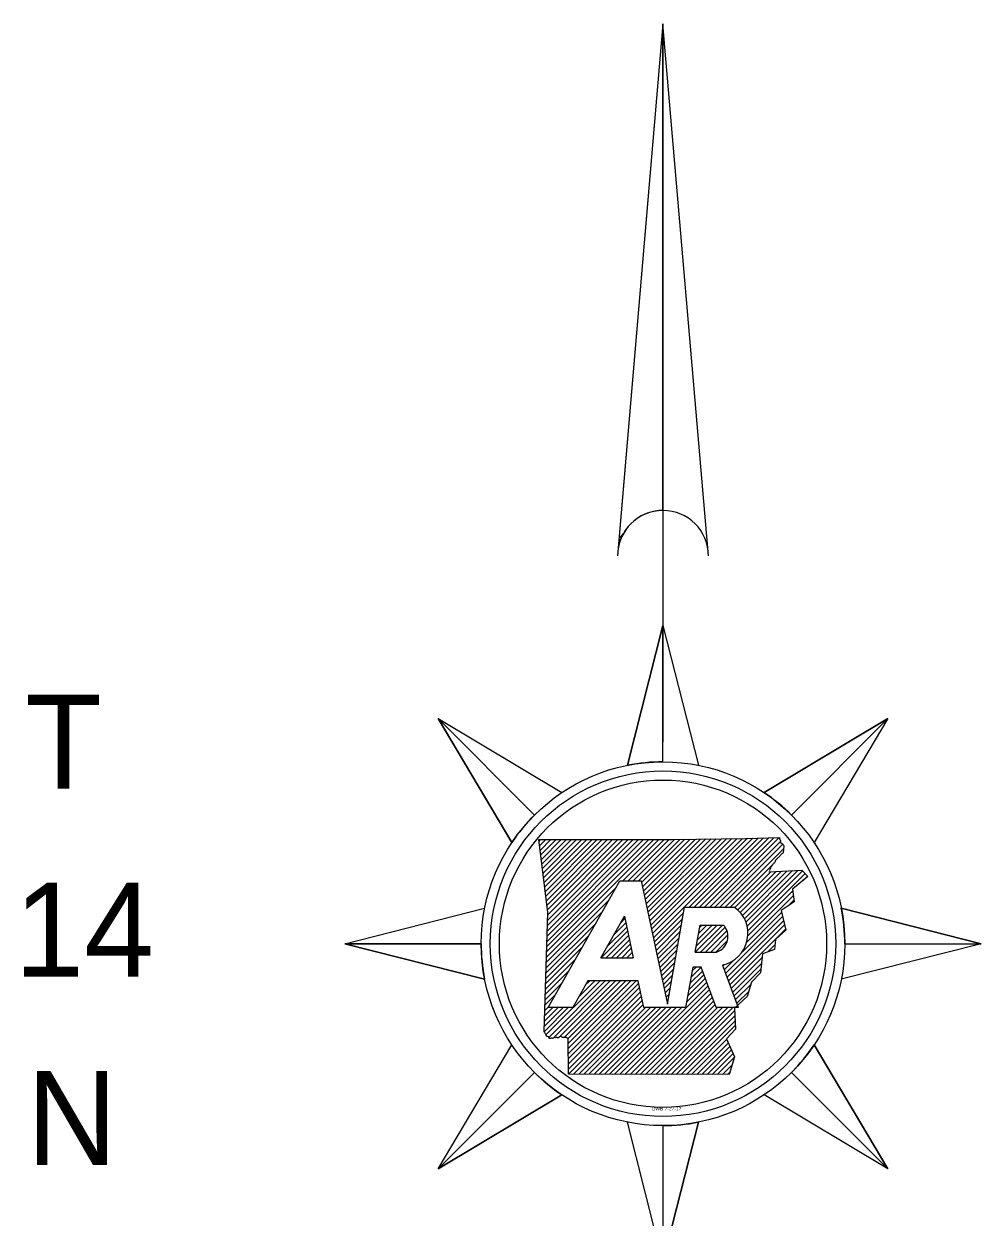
# Model space of a CAD drawing. Extents: x 309348 to 309445, y 336383 to 336484.
# Drawn here: x 309372.414 to 309374.142, y 336389.15 to 336391.302 of the extents above; entities that cross this region are included whole.
import ezdxf

# ---------------------------------------------------------------- set-up
doc = ezdxf.new("R2010")
doc.units = 0
doc.layers.add('R_Annotation', color=7, linetype='Continuous')

msp = doc.modelspace()

# ---------------------------------------------------------------- linework, layer by layer
at = {"layer": 'R_Annotation'}
for p, q in [((309373.5677, 336391.302), (309373.4868, 336390.3563)), ((309373.5677, 336391.302), (309373.5677, 336390.0068)), ((309373.5677, 336390.4244), (309373.5677, 336391.302)), ((309373.488, 336390.3695), (309373.4917, 336390.3732)), ((309373.4884, 336390.3745), (309373.4959, 336390.382)), ((309373.5677, 336390.217), (309373.5038, 336389.9647)), ((309373.5677, 336389.971), (309373.5677, 336390.217)), ((309373.1617, 336390.0489), (309373.3357, 336389.8749)), ((309373.3357, 336389.8749), (309373.1617, 336390.0489)), ((309373.1617, 336390.0489), (309373.295, 336389.8253)), ((309373.9737, 336390.0489), (309373.7501, 336389.9156)), ((309373.7997, 336389.8749), (309373.9737, 336390.0489)), ((309373.7997, 336389.8749), (309373.9737, 336390.0489)), ((309373.539, 336389.7072), (309373.6638, 336389.8321)), ((309373.5406, 336389.6996), (309373.6733, 336389.8322)), ((309373.5422, 336389.6919), (309373.6827, 336389.8324)), ((309373.5439, 336389.6843), (309373.6921, 336389.8325)), ((309373.5455, 336389.6766), (309373.7016, 336389.8327)), ((309373.5471, 336389.669), (309373.711, 336389.8328)), ((309373.5488, 336389.6613), (309373.7204, 336389.833)), ((309373.5504, 336389.6537), (309373.7299, 336389.8332)), ((309373.6149, 336389.7089), (309373.7394, 336389.8334)), ((309373.6241, 336389.7089), (309373.7489, 336389.8337)), ((309373.6334, 336389.7089), (309373.7584, 336389.8339)), ((309373.6427, 336389.7089), (309373.7679, 336389.8341)), ((309373.652, 336389.7089), (309373.7774, 336389.8343)), ((309373.344, 336389.8278), (309373.3469, 336389.8307)), ((309373.3451, 336389.8195), (309373.3562, 336389.8307)), ((309373.3461, 336389.8113), (309373.3655, 336389.8307)), ((309373.3471, 336389.803), (309373.3748, 336389.8307)), ((309373.3482, 336389.7948), (309373.384, 336389.8307)), ((309373.3492, 336389.7865), (309373.3933, 336389.8307)), ((309373.3502, 336389.7783), (309373.4026, 336389.8307)), ((309373.3512, 336389.77), (309373.4119, 336389.8306)), ((309373.3523, 336389.7618), (309373.4211, 336389.8306)), ((309373.3533, 336389.7535), (309373.4304, 336389.8306)), ((309373.3543, 336389.7453), (309373.4397, 336389.8306)), ((309373.3554, 336389.737), (309373.449, 336389.8306)), ((309373.3564, 336389.7288), (309373.4582, 336389.8306)), ((309373.3574, 336389.7205), (309373.4675, 336389.8306)), ((309373.3577, 336389.628), (309373.5605, 336389.8308)), ((309373.358, 336389.6376), (309373.5512, 336389.8308)), ((309373.3584, 336389.6472), (309373.5419, 336389.8308)), ((309373.3584, 336389.7123), (309373.4768, 336389.8306)), ((309373.3587, 336389.6568), (309373.5326, 336389.8307)), ((309373.359, 336389.6664), (309373.5233, 336389.8307)), ((309373.3593, 336389.676), (309373.514, 336389.8307)), ((309373.3595, 336389.704), (309373.4861, 336389.8306)), ((309373.3596, 336389.6856), (309373.5047, 336389.8307)), ((309373.3599, 336389.6952), (309373.4954, 336389.8307)), ((309373.4955, 336389.7566), (309373.5698, 336389.8308)), ((309373.5048, 336389.7566), (309373.5791, 336389.8308)), ((309373.5141, 336389.7566), (309373.5884, 336389.8309)), ((309373.5234, 336389.7566), (309373.5979, 336389.8311)), ((309373.5291, 336389.7531), (309373.6073, 336389.8312)), ((309373.5308, 336389.7454), (309373.6167, 336389.8314)), ((309373.5324, 336389.7378), (309373.6261, 336389.8315)), ((309373.534, 336389.7301), (309373.6356, 336389.8317)), ((309373.5357, 336389.7225), (309373.645, 336389.8318)), ((309373.5373, 336389.7148), (309373.6544, 336389.8319)), ((309373.6613, 336389.7089), (309373.7795, 336389.8271)), ((309373.6705, 336389.7089), (309373.784, 336389.8223)), ((309373.6798, 336389.7089), (309373.7852, 336389.8142)), ((309373.6891, 336389.7089), (309373.764, 336389.7838)), ((309373.6975, 336389.708), (309373.7622, 336389.7727)), ((309373.7026, 336389.7038), (309373.772, 336389.7732)), ((309373.7071, 336389.6991), (309373.7817, 336389.7737)), ((309373.7111, 336389.6938), (309373.7915, 336389.7742)), ((309373.7146, 336389.688), (309373.8013, 336389.7747)), ((309373.7174, 336389.6815), (309373.8111, 336389.7752)), ((309373.7196, 336389.6744), (309373.8199, 336389.7747)), ((309373.7208, 336389.6663), (309373.8242, 336389.7698)), ((309373.3605, 336389.528), (309373.4899, 336389.7566)), ((309373.4899, 336389.7566), (309373.5284, 336389.7566)), ((309373.8201, 336389.7564), (309373.8286, 336389.7648)), ((309373.3574, 336389.6184), (309373.4826, 336389.7437)), ((309373.7189, 336389.6459), (309373.8032, 336389.7301)), ((309373.7209, 336389.6571), (309373.8021, 336389.7383)), ((309373.3571, 336389.6088), (309373.4705, 336389.7223)), ((309373.6065, 336389.7089), (309373.6964, 336389.7089)), ((309373.7928, 336389.7104), (309373.8042, 336389.7219)), ((309374.1418, 336389.6429), (309373.8895, 336389.7068)), ((309373.3568, 336389.5992), (309373.4584, 336389.7009)), ((309373.4557, 336389.6177), (309373.498, 336389.6925)), ((309373.4915, 336389.6808), (309373.4989, 336389.6883)), ((309373.552, 336389.646), (309373.6047, 336389.6987)), ((309373.5537, 336389.6384), (309373.6027, 336389.6875)), ((309373.6806, 336389.589), (309373.7835, 336389.6919)), ((309373.6831, 336389.5822), (309373.7852, 336389.6844)), ((309373.7109, 336389.6285), (309373.7818, 336389.6994)), ((309373.3564, 336389.5896), (309373.4463, 336389.6795)), ((309373.4561, 336389.6177), (309373.5038, 336389.6654)), ((309373.4672, 336389.638), (309373.5022, 336389.673)), ((309373.4793, 336389.6594), (309373.5006, 336389.6807)), ((309373.5553, 336389.6308), (309373.6008, 336389.6762)), ((309373.5569, 336389.6231), (309373.5988, 336389.665)), ((309373.626, 336389.6278), (309373.6749, 336389.6766)), ((309373.6279, 336389.639), (309373.6656, 336389.6766)), ((309373.6299, 336389.6502), (309373.6563, 336389.6766)), ((309373.6318, 336389.6614), (309373.647, 336389.6766)), ((309373.6338, 336389.6727), (309373.6377, 336389.6766)), ((309373.6345, 336389.6766), (309373.6767, 336389.6766)), ((309373.6353, 336389.6278), (309373.68, 336389.6725)), ((309373.6446, 336389.6278), (309373.6831, 336389.6663)), ((309373.6856, 336389.5755), (309373.787, 336389.6768)), ((309373.6881, 336389.5687), (309373.7887, 336389.6693)), ((309372.9935, 336389.6429), (309373.2396, 336389.6429)), ((309373.2396, 336389.6429), (309372.9935, 336389.6429)), ((309372.9935, 336389.6429), (309373.2459, 336389.579)), ((309373.3561, 336389.58), (309373.4342, 336389.6581)), ((309373.4654, 336389.6177), (309373.5055, 336389.6577)), ((309373.4747, 336389.6177), (309373.5071, 336389.6501)), ((309373.484, 336389.6177), (309373.5087, 336389.6424)), ((309373.5586, 336389.6155), (309373.5969, 336389.6537)), ((309373.5602, 336389.6078), (309373.5949, 336389.6425)), ((309373.6539, 336389.6278), (309373.6849, 336389.6588)), ((309373.6632, 336389.6278), (309373.6841, 336389.6487)), ((309373.757, 336389.6283), (309373.77, 336389.6413)), ((309373.8958, 336389.6429), (309374.1418, 336389.6429)), ((309373.8958, 336389.6429), (309374.1418, 336389.6429)), ((309373.3558, 336389.5704), (309373.422, 336389.6367)), ((309373.4557, 336389.6177), (309373.514, 336389.6177)), ((309373.4933, 336389.6177), (309373.5104, 336389.6348)), ((309373.5025, 336389.6177), (309373.512, 336389.6271)), ((309373.5118, 336389.6177), (309373.5137, 336389.6195)), ((309373.5619, 336389.6002), (309373.5929, 336389.6313)), ((309373.5635, 336389.5925), (309373.591, 336389.62)), ((309373.626, 336389.6278), (309373.6645, 336389.6278)), ((309373.6906, 336389.5619), (309373.7463, 336389.6176)), ((309373.3555, 336389.5608), (309373.4099, 336389.6153)), ((309373.5651, 336389.5849), (309373.589, 336389.6088)), ((309373.5668, 336389.5773), (309373.5871, 336389.5976)), ((309373.618, 336389.5821), (309373.6366, 336389.6007)), ((309373.62, 336389.5933), (309373.6273, 336389.6007)), ((309373.6368, 336389.6007), (309373.6213, 336389.6007)), ((309373.6637, 336389.528), (309373.6368, 336389.6007)), ((309373.6749, 336389.6045), (309373.7032, 336389.528)), ((309373.6756, 336389.6026), (309373.6784, 336389.6054)), ((309373.6781, 336389.5958), (309373.6958, 336389.6135)), ((309373.6931, 336389.5551), (309373.7453, 336389.6073)), ((309373.6956, 336389.5484), (309373.7442, 336389.5969)), ((309373.3552, 336389.5513), (309373.3978, 336389.5939)), ((309373.3565, 336389.4784), (309373.4541, 336389.5759)), ((309373.3621, 336389.4746), (309373.4634, 336389.5759)), ((309373.3687, 336389.472), (309373.4726, 336389.5759)), ((309373.3797, 336389.4738), (309373.4819, 336389.5759)), ((309373.3892, 336389.4739), (309373.4912, 336389.5759)), ((309373.3964, 336389.4719), (309373.5005, 336389.5759)), ((309373.3968, 336389.4537), (309373.519, 336389.5759)), ((309373.3968, 336389.4629), (309373.5098, 336389.5759)), ((309373.4321, 336389.5759), (309373.4049, 336389.528)), ((309373.4154, 336389.5465), (309373.4448, 336389.5759)), ((309373.4275, 336389.5679), (309373.4355, 336389.5759)), ((309373.523, 336389.5759), (309373.4321, 336389.5759)), ((309373.5684, 336389.5696), (309373.5851, 336389.5863)), ((309373.57, 336389.562), (309373.5832, 336389.5751)), ((309373.6121, 336389.5484), (309373.6443, 336389.5805)), ((309373.6141, 336389.5596), (309373.6418, 336389.5873)), ((309373.6161, 336389.5709), (309373.6393, 336389.5941)), ((309373.3549, 336389.5417), (309373.3857, 336389.5725)), ((309373.3968, 336389.4444), (309373.5239, 336389.5715)), ((309373.3968, 336389.4351), (309373.5256, 336389.5639)), ((309373.3968, 336389.4259), (309373.5272, 336389.5562)), ((309373.4897, 336389.4074), (309373.6493, 336389.567)), ((309373.4989, 336389.4073), (309373.6518, 336389.5602)), ((309373.5082, 336389.4073), (309373.6543, 336389.5534)), ((309373.5717, 336389.5543), (309373.5812, 336389.5638)), ((309373.5733, 336389.5467), (309373.5792, 336389.5526)), ((309373.6102, 336389.5372), (309373.6468, 336389.5737)), ((309373.6981, 336389.5416), (309373.7266, 336389.57)), ((309373.7006, 336389.5348), (309373.7226, 336389.5568)), ((309373.3545, 336389.5321), (309373.3736, 336389.5511)), ((309373.3969, 336389.4166), (309373.5288, 336389.5486)), ((309373.397, 336389.4075), (309373.5305, 336389.541)), ((309373.4063, 336389.4075), (309373.5321, 336389.5333)), ((309373.5175, 336389.4073), (309373.6568, 336389.5466)), ((309373.5267, 336389.4073), (309373.6593, 336389.5399)), ((309373.536, 336389.4073), (309373.6618, 336389.5331)), ((309373.5749, 336389.539), (309373.5773, 336389.5414)), ((309373.3531, 336389.4842), (309373.3968, 336389.528)), ((309373.3533, 336389.4937), (309373.3875, 336389.528)), ((309373.3536, 336389.5033), (309373.3783, 336389.528)), ((309373.3539, 336389.5129), (309373.369, 336389.528)), ((309373.3542, 336389.5225), (309373.3615, 336389.5297)), ((309373.4049, 336389.528), (309373.3605, 336389.528)), ((309373.4156, 336389.4075), (309373.536, 336389.528)), ((309373.4248, 336389.4075), (309373.5453, 336389.528)), ((309373.4341, 336389.4075), (309373.5546, 336389.528)), ((309373.4433, 336389.4074), (309373.5639, 336389.528)), ((309373.4526, 336389.4074), (309373.5731, 336389.528)), ((309373.4619, 336389.4074), (309373.5824, 336389.528)), ((309373.4711, 336389.4074), (309373.5917, 336389.528)), ((309373.4804, 336389.4074), (309373.601, 336389.528)), ((309373.6086, 336389.528), (309373.5332, 336389.528)), ((309373.5453, 336389.4073), (309373.6659, 336389.528)), ((309373.5545, 336389.4073), (309373.6752, 336389.528)), ((309373.5638, 336389.4072), (309373.6845, 336389.528)), ((309373.5731, 336389.4072), (309373.6938, 336389.528)), ((309373.5823, 336389.4072), (309373.6969, 336389.5218)), ((309373.5916, 336389.4072), (309373.6973, 336389.5129)), ((309373.7032, 336389.528), (309373.6637, 336389.528)), ((309373.6008, 336389.4072), (309373.6977, 336389.504)), ((309373.6101, 336389.4072), (309373.6981, 336389.4952)), ((309373.6194, 336389.4071), (309373.6829, 336389.4707)), ((309373.6286, 336389.4071), (309373.6858, 336389.4642)), ((309373.6379, 336389.4071), (309373.6886, 336389.4578)), ((309373.6472, 336389.4071), (309373.6915, 336389.4514)), ((309373.6564, 336389.4071), (309373.6943, 336389.445)), ((309373.9737, 336389.2369), (309373.8404, 336389.4605)), ((309373.6657, 336389.4071), (309373.6967, 336389.4381)), ((309373.675, 336389.4071), (309373.6925, 336389.4246)), ((309373.1617, 336389.2369), (309373.3357, 336389.4109)), ((309373.3357, 336389.4109), (309373.1617, 336389.2369)), ((309373.6842, 336389.407), (309373.6883, 336389.4112)), ((309373.7997, 336389.4109), (309373.9737, 336389.2369)), ((309373.7997, 336389.4109), (309373.9737, 336389.2369)), ((309373.1617, 336389.2369), (309373.3853, 336389.3702)), ((309373.5677, 336389.0687), (309373.6316, 336389.3211)), ((309373.5677, 336389.3148), (309373.5677, 336389.3148)), ((309373.5677, 336389.3148), (309373.5677, 336388.2645)), ((309373.5677, 336389.3148), (309373.5677, 336389.0687))]:
    msp.add_line(p, q, dxfattribs=at)
for points in [[(309373.6497, 336390.3424), (309373.5677, 336391.302), (309373.4857, 336390.3424)], [(309373.5038, 336389.9647), (309373.5677, 336390.217), (309373.6316, 336389.9647)], [(309373.295, 336389.8253), (309373.1617, 336390.0489), (309373.3853, 336389.9156)], [(309373.7501, 336389.9156), (309373.9737, 336390.0489), (309373.8404, 336389.8253)], [(309373.3437, 336389.8307), (309373.4717, 336389.8306), (309373.5841, 336389.8309), (309373.7166, 336389.8329), (309373.778, 336389.8343)], [(309373.353, 336389.4843), (309373.3601, 336389.6991), (309373.3437, 336389.8307)], [(309373.8182, 336389.7755), (309373.8293, 336389.7639), (309373.8017, 336389.7412), (309373.8047, 336389.7183), (309373.781, 336389.7027), (309373.7891, 336389.6675), (309373.7708, 336389.6508), (309373.7692, 336389.6327), (309373.747, 336389.6247), (309373.7436, 336389.5905), (309373.7276, 336389.5734), (309373.7199, 336389.5477), (309373.6967, 336389.5264), (309373.6984, 336389.4889), (309373.6826, 336389.4712), (309373.697, 336389.439), (309373.6871, 336389.407)], [(309373.759, 336389.7725), (309373.8191, 336389.7756)], [(309373.5284, 336389.7566), (309373.576, 336389.5341), (309373.6065, 336389.7089)], [(309373.2459, 336389.579), (309372.9935, 336389.6429), (309373.2459, 336389.7068)], [(309373.8895, 336389.7068), (309374.1418, 336389.6429), (309373.8895, 336389.579)], [(309373.498, 336389.6925), (309373.514, 336389.6177)], [(309373.626, 336389.6278), (309373.6345, 336389.6766)], [(309373.6213, 336389.6007), (309373.6086, 336389.528)], [(309373.5332, 336389.528), (309373.523, 336389.5759)], [(309373.6871, 336389.407), (309373.3969, 336389.4075), (309373.3967, 336389.4716)], [(309373.3853, 336389.3702), (309373.1617, 336389.2369), (309373.295, 336389.4605)], [(309373.8404, 336389.4605), (309373.9737, 336389.2369), (309373.7501, 336389.3702)], [(309373.6316, 336389.3211), (309373.5677, 336389.0687), (309373.5038, 336389.3211)]]:
    msp.add_lwpolyline(points, dxfattribs=at)
for radius in [0.3281, 0.3117, 0.2953]:
    msp.add_circle((309373.5677, 336389.6429), radius, dxfattribs=at)
for centre, radius, start, end in [((309373.5677, 336390.3424), 0.082, 0, 180), ((309373.5677, 336390.3424), 0.082, 90, 170.2296), ((309373.5677, 336389.6429), 0.3281, 90, 101.2291), ((309373.5677, 336389.6429), 0.3281, 45, 56.2291), ((309373.5677, 336389.6429), 0.3281, 135, 146.2291), ((309373.6629, 336389.6614), 0.0581, 281.8626, 54.8705), ((309373.5677, 336389.6429), 0.3281, 0, 11.2291), ((309373.6553, 336389.656), 0.0297, 288.1268, 43.8902), ((309373.5677, 336389.6429), 0.3281, 180, 191.2291), ((309373.5677, 336389.6429), 0.3281, 315, 326.2291), ((309373.5677, 336389.6429), 0.3281, 225, 236.2291), ((309373.5677, 336389.6429), 0.3281, 270, 281.2291)]:
    msp.add_arc(centre, radius, start, end, dxfattribs=at)
for points in [[(309373.778, 336389.8343), (309373.7784, 336389.8309), (309373.7795, 336389.829), (309373.7797, 336389.8257), (309373.781, 336389.8243), (309373.7833, 336389.8229), (309373.7854, 336389.8206), (309373.7859, 336389.8179), (309373.7852, 336389.8151), (309373.7851, 336389.812), (309373.7848, 336389.8093), (309373.7843, 336389.8069), (309373.7824, 336389.8049), (309373.7806, 336389.8035), (309373.7789, 336389.8018), (309373.7777, 336389.8001), (309373.7757, 336389.7982), (309373.7736, 336389.7962), (309373.7719, 336389.7944), (309373.7703, 336389.7922), (309373.7695, 336389.7898), (309373.7677, 336389.788), (309373.7662, 336389.7864), (309373.7643, 336389.7843), (309373.7634, 336389.7822), (309373.7616, 336389.7797), (309373.7612, 336389.7773), (309373.76, 336389.7754), (309373.7599, 336389.7751)], [(309373.3967, 336389.4716), (309373.397, 336389.4714), (309373.3955, 336389.4724), (309373.3935, 336389.4735), (309373.3912, 336389.4736), (309373.3883, 336389.474), (309373.3858, 336389.4743), (309373.3833, 336389.4759), (309373.3806, 336389.4742), (309373.3776, 336389.4729), (309373.3758, 336389.4743), (309373.3735, 336389.4734), (309373.372, 336389.4739), (309373.3692, 336389.472), (309373.3666, 336389.4727), (309373.3647, 336389.4721), (309373.3623, 336389.4722), (309373.3618, 336389.4749), (309373.3595, 336389.4753), (309373.3575, 336389.4764), (309373.3562, 336389.4792), (309373.3552, 336389.4813), (309373.353, 336389.4843)]]:
    msp.add_spline(points, degree=3, dxfattribs=at)

# ---------------------------------------------------------------- texts
for s, height, p in [('T', 0.1696, (309372.4167, 336389.9224)), ('14', 0.16963, (309372.3971, 336389.5832)), ('N', 0.1696, (309372.4192, 336389.2439)), ('DWB 7-27-17', 0.006379, (309373.5476, 336389.3421))]:
    msp.add_text(s, height=height, dxfattribs=at).set_placement(p)

doc.saveas('drawing.dxf')
